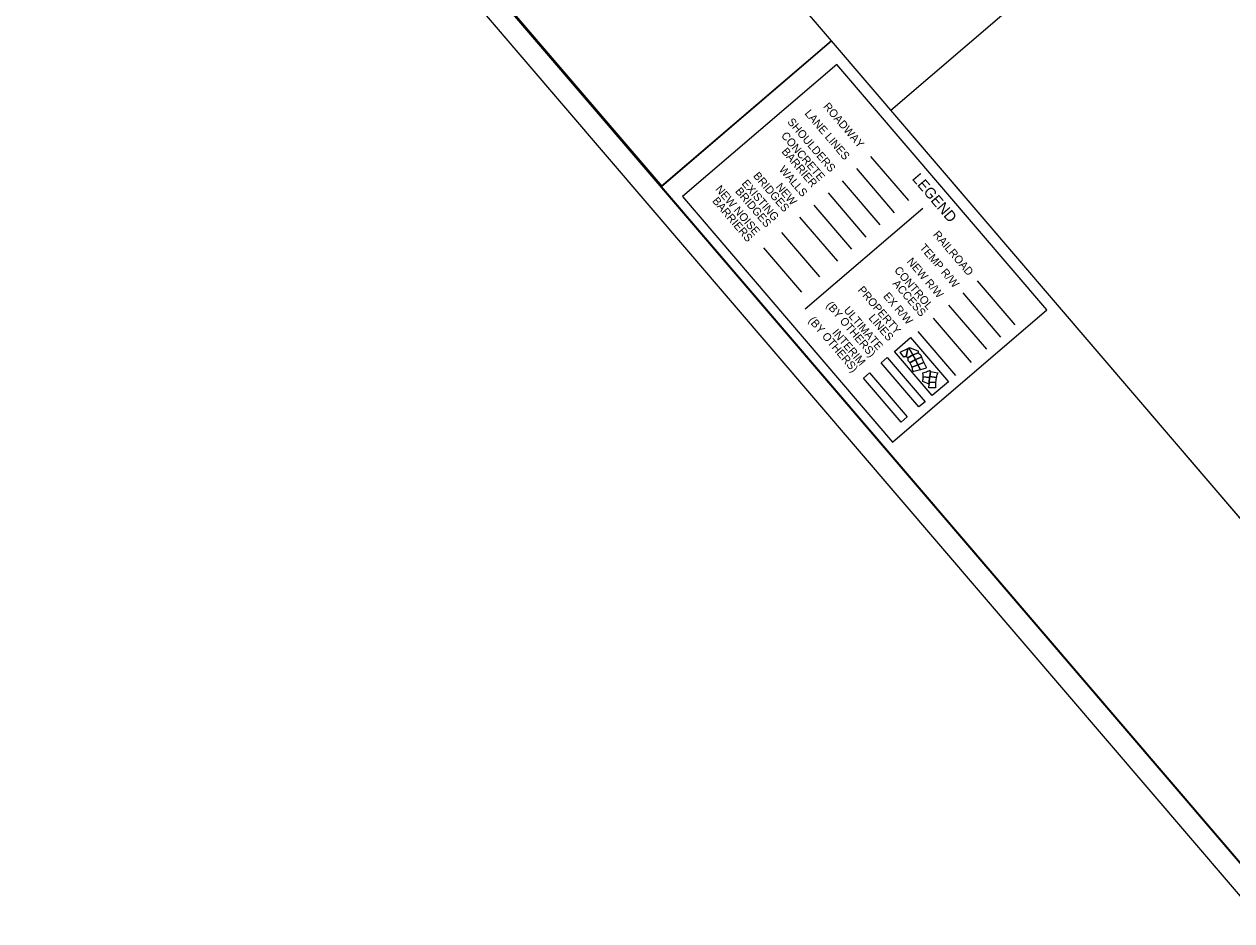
# Model space of a CAD drawing. Extents: x 1941897 to 1978064, y 805467 to 836604.
# Drawn here: x 1943528 to 1949186, y 821550 to 825752 of the extents above; entities that cross this region are included whole.
import ezdxf

# ---------------------------------------------------------------- set-up
doc = ezdxf.new("R2010")
doc.units = 0
for name, color, linetype in [('Default', 7, 'Continuous'), ('RD_EX_H20_TX', 7, 'Continuous'), ('RD_SHT_Bndy', 7, 'Continuous'), ('RD_SHT_IplotShp', 7, 'Continuous'), ('RD_SHT_TX', 7, 'Continuous'), ('RD_Sketch1', 7, 'Continuous')]:
    doc.layers.add(name, color=color, linetype=linetype)

msp = doc.modelspace()

# ---------------------------------------------------------------- linework, layer by layer
at = {"layer": 'Default'}
for points in [[(1947659.6, 824193.7), (1947658.3, 824193.9), (1947656.8, 824194), (1947655.2, 824193.9), (1947653.6, 824193.6), (1947652.1, 824193.1), (1947650.7, 824192.4), (1947649.4, 824191.6), (1947631.8, 824215.3), (1947667.4, 824232.7)], [(1947690.6, 824202.7), (1947667.4, 824188.2), (1947666.5, 824189.5), (1947665.4, 824190.6), (1947664.2, 824191.6), (1947662.8, 824192.5), (1947661.4, 824193.2), (1947659.6, 824193.7), (1947667.4, 824232.7), (1947671.9, 824235)], [(1947717.2, 824220.3), (1947716.8, 824218.5), (1947716.6, 824217), (1947716.7, 824215.4), (1947716.9, 824213.8), (1947717.4, 824212.3), (1947690.6, 824202.7), (1947671.9, 824235), (1947676.3, 824237.1)], [(1947723.9, 824205.2), (1947725.1, 824204.5), (1947726.2, 824203.7), (1947727.2, 824202.7), (1947728.1, 824201.5), (1947729.1, 824199.4), (1947731.9, 824191), (1947703.5, 824180.5), (1947690.6, 824202.7), (1947717.4, 824212.3), (1947718.2, 824210.5), (1947719, 824209.2), (1947720, 824208), (1947721.2, 824206.9), (1947722.5, 824206)], [(1947703.5, 824180.5), (1947677.3, 824165.3), (1947676.6, 824166.2), (1947674.4, 824169), (1947672, 824171.6), (1947671.6, 824172), (1947670.7, 824173.1), (1947670.1, 824174.4), (1947669.6, 824175.7), (1947669.2, 824177.1), (1947669.1, 824178.5), (1947669.2, 824179.9), (1947669.3, 824180.6), (1947669.3, 824182.2), (1947669.1, 824183.8), (1947668.7, 824185.3), (1947668.2, 824186.8), (1947667.4, 824188.2), (1947690.6, 824202.7)], [(1947715.3, 824155.7), (1947687.5, 824144.3), (1947687.1, 824146.1), (1947686.6, 824147.6), (1947685.4, 824150.9), (1947684, 824154.2), (1947682.4, 824157.3), (1947680.6, 824160.4), (1947678.7, 824163.4), (1947677.3, 824165.3), (1947703.5, 824180.5)], [(1947726.8, 824131.6), (1947696.2, 824124.4), (1947695.5, 824124.3), (1947694.7, 824124.4), (1947693.8, 824124.6), (1947693.1, 824125), (1947692.5, 824125.6), (1947692, 824126.4), (1947691.7, 824127.2), (1947687.5, 824144.3), (1947715.3, 824155.7)], [(1947742.9, 824165.9), (1947715.3, 824155.7), (1947703.5, 824180.5), (1947731.9, 824191), (1947736.1, 824178.7)], [(1947726.8, 824131.6), (1947715.3, 824155.7), (1947742.9, 824165.9), (1947754, 824145), (1947754.3, 824144), (1947754.4, 824143.2), (1947754.3, 824142.3), (1947754, 824141.5), (1947753.5, 824140.8), (1947752.9, 824140.2), (1947752.1, 824139.8), (1947748.7, 824138.4), (1947743.4, 824136.4), (1947738, 824134.6), (1947732.5, 824133)], [(1947770.1, 824095.4), (1947767.6, 824074.3), (1947767.1, 824065.5), (1947737.4, 824077.1), (1947738.1, 824080), (1947738.9, 824084.2), (1947739.4, 824088.4), (1947739.8, 824092.6), (1947740, 824096.9), (1947740, 824100)], [(1947773.5, 824123.7), (1947770.9, 824101.6), (1947770.1, 824095.4), (1947740, 824100), (1947740, 824101.1), (1947739.7, 824105.3), (1947739.3, 824109.5), (1947738.7, 824113.7), (1947738, 824117.4), (1947743.7, 824119.1), (1947749.4, 824121), (1947755, 824123.1), (1947760.5, 824125.4), (1947766, 824127.9), (1947770.2, 824130)], [(1947801, 824095.9), (1947800.3, 824092.4), (1947799.2, 824086.6), (1947798.4, 824080.8), (1947797.7, 824075), (1947797.6, 824073.2), (1947767.6, 824074.3), (1947770.1, 824095.4), (1947770.9, 824101.6)], [(1947807.7, 824118.7), (1947806.4, 824115.1), (1947804.6, 824109.5), (1947802.9, 824103.8), (1947801.5, 824098.1), (1947801, 824095.9), (1947770.9, 824101.6), (1947773.5, 824123.7)], [(1947797.6, 824073.2), (1947797.3, 824069.2), (1947797.2, 824067.8), (1947797.2, 824048.2), (1947766.2, 824048), (1947767.1, 824065.5), (1947767.6, 824074.3)]]:
    msp.add_lwpolyline(points, close=True, dxfattribs=at)
at = {"layer": 'RD_EX_H20_TX'}
msp.add_lwpolyline([(1963151.2, 810860.3), (1959509.3, 815114.3), (1958096.8, 813905.1), (1957040.5, 814307.7), (1947588.1, 825348.6), (1952108, 829218.2), (1965848, 813169.1)], close=True, dxfattribs=at)
msp.add_lwpolyline([(1963151.2, 810860.3), (1959509.3, 815114.3), (1958096.8, 813905.1), (1957040.5, 814307.7), (1947588.1, 825348.6), (1952108, 829218.2), (1965848, 813169.1)], close=True, dxfattribs=at)
msp.add_lwpolyline([(1963151.2, 810860.3), (1959509.3, 815114.3), (1958096.8, 813905.1), (1957040.5, 814307.7), (1947588.1, 825348.6), (1952108, 829218.2), (1965848, 813169.1)], close=True, dxfattribs=at)
at = {"layer": 'RD_SHT_Bndy'}
msp.add_line((1947738, 824888.3), (1947186.2, 824416.1), dxfattribs=at)
for points in [[(1960707.9, 808409.5), (1943668.8, 828312), (1948986.3, 832864.4), (1966025.3, 812961.9)], [(1945335.5, 826370.9), (1946515, 824993.2), (1947309.9, 825673.6), (1946130.4, 827051.4)], [(1946512.2, 824990.8), (1956970, 812775.5), (1957767.7, 813458.3), (1947309.9, 825673.6)], [(1946611.9, 824943.8), (1947596.1, 823793.9), (1948319, 824412.6), (1947334.8, 825562.5)], [(1947680.7, 824283), (1947857.7, 824076.2), (1947781.7, 824011.2), (1947604.7, 824218)]]:
    msp.add_lwpolyline(points, close=True, dxfattribs=at)
at = {"layer": 'RD_SHT_IplotShp'}
msp.add_lwpolyline([(1960696.9, 808268.5), (1943527.9, 828323), (1948997.3, 833005.4), (1966166.3, 812950.9)], close=True, dxfattribs=at)
at = {"layer": 'RD_Sketch1'}
for p, q in [((1947493.4, 825131.9), (1947670.4, 824925.1)), ((1947426.9, 825075), (1947603.9, 824868.2)), ((1947360.4, 825018.1), (1947537.4, 824811.3)), ((1947294, 824961.2), (1947470.9, 824754.4)), ((1947227.5, 824904.3), (1947404.5, 824697.5)), ((1947161, 824847.4), (1947338, 824640.6)), ((1947076.7, 824775.3), (1947253.7, 824568.5)), ((1946992.4, 824703.1), (1947169.4, 824496.4)), ((1947992, 824549.4), (1948169, 824342.6)), ((1947925.5, 824492.5), (1948102.5, 824285.7)), ((1947859, 824435.6), (1948036, 824228.8)), ((1947787, 824373.9), (1947963.9, 824167.1)), ((1947714.5, 824311.8), (1947891.5, 824105.1))]:
    msp.add_line(p, q, dxfattribs=at)
for points in [[(1947571.5, 824189.4), (1947748.5, 823982.6), (1947720, 823958.2), (1947543, 824165)], [(1947488.3, 824118.2), (1947665.3, 823911.4), (1947636.8, 823887), (1947459.8, 824093.8)]]:
    msp.add_lwpolyline(points, close=True, dxfattribs=at)

# ---------------------------------------------------------------- texts
at = {"layer": 'RD_SHT_TX'}
for s, height, p in [('LANE LINES', 37.5, (1947182.3, 825331.9)), ('ROADWAY', 37.5, (1947269.6, 825364.5)), ('SHOULDERS', 37.5, (1947101.2, 825292.2)), ('CONCRETE', 37.5, (1947071.9, 825227.9)), ('BARRIER', 37.5, (1947074, 825153.3)), ('BRIDGES', 37.5, (1946941, 825039.6)), ('WALLS', 37.5, (1947062.1, 825068.7)), ('EXISTING', 37.5, (1946887.3, 825003.8)), ('NEW', 37.5, (1947047, 824987.8)), ('LEGEND', 50, (1947685, 825026.2)), ('BARRIERS', 37.5, (1946749.5, 824922)), ('NEW NOISE', 37.5, (1946764, 824977.2)), ('BRIDGES', 37.5, (1946856.7, 824967.4)), ('RAILROAD', 37.5, (1947783.6, 824764)), ('TEMP R/W', 37.5, (1947720.4, 824703.3)), ('CONTROL', 37.5, (1947601.9, 824597.2)), ('NEW R/W ', 37.5, (1947661.1, 824637.9)), ('ACCESS', 37.5, (1947593.9, 824534.5)), ('PROPERTY ', 37.5, (1947431.3, 824504.6)), ('EX R/W ', 37.5, (1947550.1, 824475.8)), ('(BY OTHERS)', 37.5, (1947283, 824433.4)), ('(BY OTHERS)', 37.5, (1947199.8, 824362.2)), ('ULTIMATE', 37.5, (1947365.1, 824409.6)), ('LINES', 37.5, (1947481.7, 824373.7)), ('INTERIM', 37.5, (1947310.9, 824304.5))]:
    msp.add_text(s, height=height, rotation=310.5604, dxfattribs=at).set_placement(p)

doc.saveas('drawing.dxf')
